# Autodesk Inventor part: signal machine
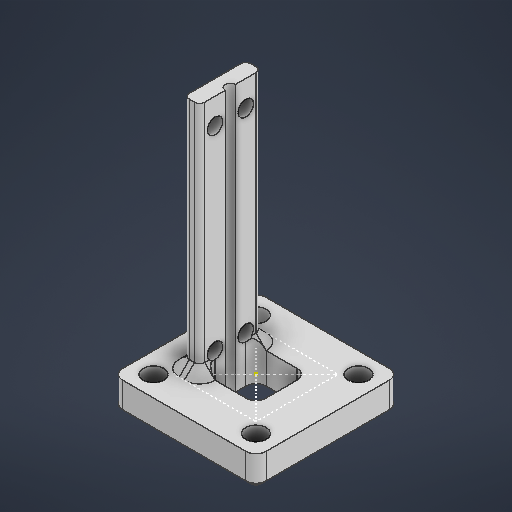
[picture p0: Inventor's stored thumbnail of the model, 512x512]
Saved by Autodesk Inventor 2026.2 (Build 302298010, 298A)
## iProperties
Created: 2026-05
Part Number: signal machine
Material: 일반
Document SubType Name: Modeling
Designer: work
Density: 1 g/cm^3
Appearance: 기본값
Author: work
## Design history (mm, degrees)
sketch "스케치1"
  geometry: L1 (-10, 10)-(10, 10); L2 (10, 10)-(10, -10); L3 (10, -10)-(-10, -10); L4 (-10, -10)-(-10, 10); L5 (-10, 10)-(10, -10); L6 (10, 10)-(-10, -10); L7 (-3, 5)-(3, 5); L8 (5, 3)-(5, -3); L9 (3, -5)-(-3, -5); L10 (-5, -3)-(-5, 3); L11 (-5, 5)-(5, -5); L12 (5, 5)-(-5, -5); L13 (-14, 14)-(14, 14); L14 (14, 14)-(14, -14); L15 (14, -14)-(-14, -14); L16 (-14, -14)-(-14, 14); L17 (-14, 14)-(14, -14); L18 (14, 14)-(-14, -14); C1 r 2 at (10, 10); C2 r 2 at (10, -10); C3 r 2 at (-10, -10); C4 r 2 at (-10, 10); A1 r 2 centre (3, 3) between (5, 3) and (3, 5); A2 r 2 centre (-3, 3) between (-3, 5) and (-5, 3); A3 r 2 centre (-3, -3) between (-5, -3) and (-3, -5); A4 r 2 centre (3, -3) between (3, -5) and (5, -3); 1 further point
  constraints: 36 end point, 8 centre point, 8 point on circle, 8 point on line, 8 tangent, 6 midpoint, 6 parallel, 4 coincident, 3 equal radius, 3 horizontal, 3 perpendicular
  dimensions: "d0" = 20 distance of L2.end L3.end; "d1" = 20 distance of L1.end L2.end; "d2" = 10 distance of L11.end L12.end; "d3" = 10 distance of L12.start L11.end; "d4" = 4 diameter of C1; "d5" = 4 diameter of C2; "d6" = 4 diameter of C3; "d7" = 4 diameter of C4; "d8" = 4 distance between parallel lines of L14 L2; "d9" = 4 distance between parallel lines of L15 L3; "d10" = 2 radius of A1 (derived)
extrude "돌출1" new body sketch "스케치1" distance "d11" = 6; taper "d12" = 0 deg
sketch "스케치2"
  geometry: 1 further point
sketch "스케치3"
  geometry: L1 (3, 0)-(3, 9); L2 (0, 9)-(6, 9); L3 (-3, 12)-(9, 12); L4 (9, 12)-(9, 0); L5 (9, 0)-(-3, 0); L6 (-3, 0)-(-3, 12); C1 r 1.5 at (0, 9); C2 r 1.5 at (6, 9); 1 further point
  constraints: 12 end point, 3 midpoint, 2 centre point, 2 coincident, 2 horizontal, 2 parallel, 1 perpendicular, 1 vertical
  dimensions: "d13" = 9 distance of L1.start L1.end; "d14" = 3 diameter of C1; "d15" = 3 diameter of C2; "d16" = 6 distance of L2.start L2.end; "d17" = 3 distance from line of point (3, 12) L2; "d18" = 3 distance from line of L4 L2.end
extrude "돌출2" join sketch "스케치3" distance "d19" = 3; taper "d20" = 0 deg
sketch "스케치4"
  geometry: L1 (0, 3)-(0, 9) reference; C1 r 1 at (0, 6); 3 further points
  constraints: 1 centre point, 1 midpoint
  dimensions: "d21" = 2 diameter of C1
extrude "돌출3" cut sketch "스케치4" extent not by distance; stored distance "d22" = 0; taper "d23" = 0 deg
fillet "모깎기1" dims "d24" = 1
fillet "모깎기3" dims "d26" = 2
sketch "스케치5"
  geometry: L1 (8, -8)-(-8, -8); L2 (-8, -8)-(-8, 8); L3 (-8, 8)-(8, 8); L4 (8, 8)-(8, -8); L5 (8, -8)-(-8, 8); L6 (-8, -8)-(8, 8); L7 (-8, -5)-(-8, 5) reference; 2 further points
  constraints: 12 end point, 4 midpoint, 2 parallel, 2 perpendicular, 1 horizontal
sketch "스케치6"
  geometry: L1 (-3, -5)-(-3, 5) reference; L2 (-1, -6)-(-2, -6) reference; L3 (0, -1)-(0, -5) reference; L4 (0, 5)-(0, 1) reference; L5 (-1, 6)-(-2, 6) reference; A1 r 1 centre (-2, 5) between (-2, 6) and (-3, 5) reference; A2 r 1 centre (-2, -5) between (-3, -5) and (-2, -6) reference; A3 r 1 centre (-1, -5) between (-1, -6) and (0, -5) reference; A4 r 1 centre (0, 0) between (0, 1) and (0, -1) reference; A5 r 1 centre (-1, 5) between (0, 5) and (-1, 6) reference; 1 further point
extrude "돌출4" join sketch "스케치6" distance "d27" = 40; taper "d28" = 0 deg
sketch "스케치7"
  geometry: L1 (0, 47)-(6, 47); L2 (3, 47)-(3, 9); L3 (4, 0)-(4, 52) reference; L4 (-2, 6)-(-2, 52) reference; L5 (0, 6)-(-2, 6) reference; L6 (0, 0)-(0, 6) reference; L7 (0, 0)-(2, 0) reference; L8 (2, 0)-(2, 52) reference; L9 (-2, 52)-(2, 52) reference; L10 (8, 6)-(8, 52) reference; L11 (4, 52)-(8, 52) reference; L12 (4, 0)-(4, 52) reference; L13 (4, 0)-(6, 0) reference; L14 (6, 0)-(6, 6) reference; L15 (8, 6)-(6, 6) reference; L16 (6, 9)-(0, 9); C1 r 1.5 at (0, 47); C2 r 1.5 at (6, 47); C3 r 1.5 at (0, 9) reference; C4 r 1.5 at (6, 9) reference; 1 further point
  constraints: 6 end point, 2 centre point, 2 coincident, 2 horizontal, 2 midpoint, 2 parallel
  dimensions: "d29" = 3 diameter of C1; "d30" = 3 diameter of C2; "d31" = 38 distance of L2.end L2.start
extrude "돌출5" cut sketch "스케치7" extent not by distance; stored distance "d32" = 0; taper "d33" = 0 deg
chamfer "모따기1" distance "d34" = 1; stored, may be unused: second distance "d35" = 2, angle "d36" = 45 deg
chamfer "모따기2" distance "d37" = 2; stored, may be unused: second distance "d38" = 2, angle "d39" = 45 deg
sketch "스케치8"
  geometry: L1 (-7.118, 8)-(-8, 8) reference; L2 (-1.118, 8)-(-4.882, 8) reference; L3 (2, 8)-(1.118, 8) reference; L4 (2, 8)-(2, 52) reference; L5 (-8, 52)-(2, 52) reference; L6 (-8, 8)-(-8, 52) reference; L7 (-6, 6)-(0, 6) reference; C1 r 1.5 at (0, 47) reference; C2 r 1.5 at (-6, 47) reference; C3 r 3 at (0, 9); A1 r 1.5 centre (-6, 9) between (-4.882, 8) and (-7.118, 8) reference; A2 r 1.5 centre (0, 9) between (1.118, 8) and (-1.118, 8) reference; 3 further points
  constraints: 2 coincident, 1 centre point, 3 other
extrude "돌출6" cut sketch "스케치8" distance "d40" = 10; taper "d41" = 0 deg
feature "ǽ耀ǿ耀ȁ耀ȃ耀ȅ耀ȇ耀ȉ耀ȋ耀" dims "d0" = 20, "d1" = 20, "d2" = 10, "d3" = 10, "d4" = 4, "d5" = 4, "d6" = 4, "d7" = 4, "d8" = 4, "d9" = 4, "d10" = 2 (derived), "d11" = 6, "d12" = 0, "d13" = 9, "d14" = 3, "d15" = 3, "d16" = 6, "d17" = 3, "d18" = 3, "d19" = 3, "d20" = 0, "d21" = 2, "d22" = 0, "d23" = 0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
node "솔리드1"
node "투영된 루프1"
node "투영된 루프2"
node "투영된 루프3"
node "투영된 루프4"
